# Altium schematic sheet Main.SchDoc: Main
size A4; Date: Not shown in title block; ApprovedBy: Not shown in title block; CheckedBy: Not shown in title block; Author: Not shown in title block; CompanyName: Not shown in title block; DrawnBy: Hely Zhang; Engineer: Hely Zhang; Organization: Texas Instrument; Address1: Not shown in title block; Address2: Not shown in title block; Address3: Not shown in title block; Address4: Not shown in title block; DocumentNumber: 2; Revision: Use project parameter SCH_Rev; SheetNumber: 2; SheetTotal: 6; PageSetup: Record=PageOptions¦CenterHorizontal=True¦CenterVertical=True¦PrintScale=1.00¦XCorrection=1.00¦YCorrection=1.00¦PrintKind=0¦BorderSize=5000000¦LeftOffset=0¦BottomOffset=0¦Orientation=2¦PaperLength=1000¦PaperWidth=1000¦Scale=100¦PaperSource=15¦PrintQuality=600¦MediaType=1¦DitherType=10¦PaperKind=Letter¦PrintScaleMode=1
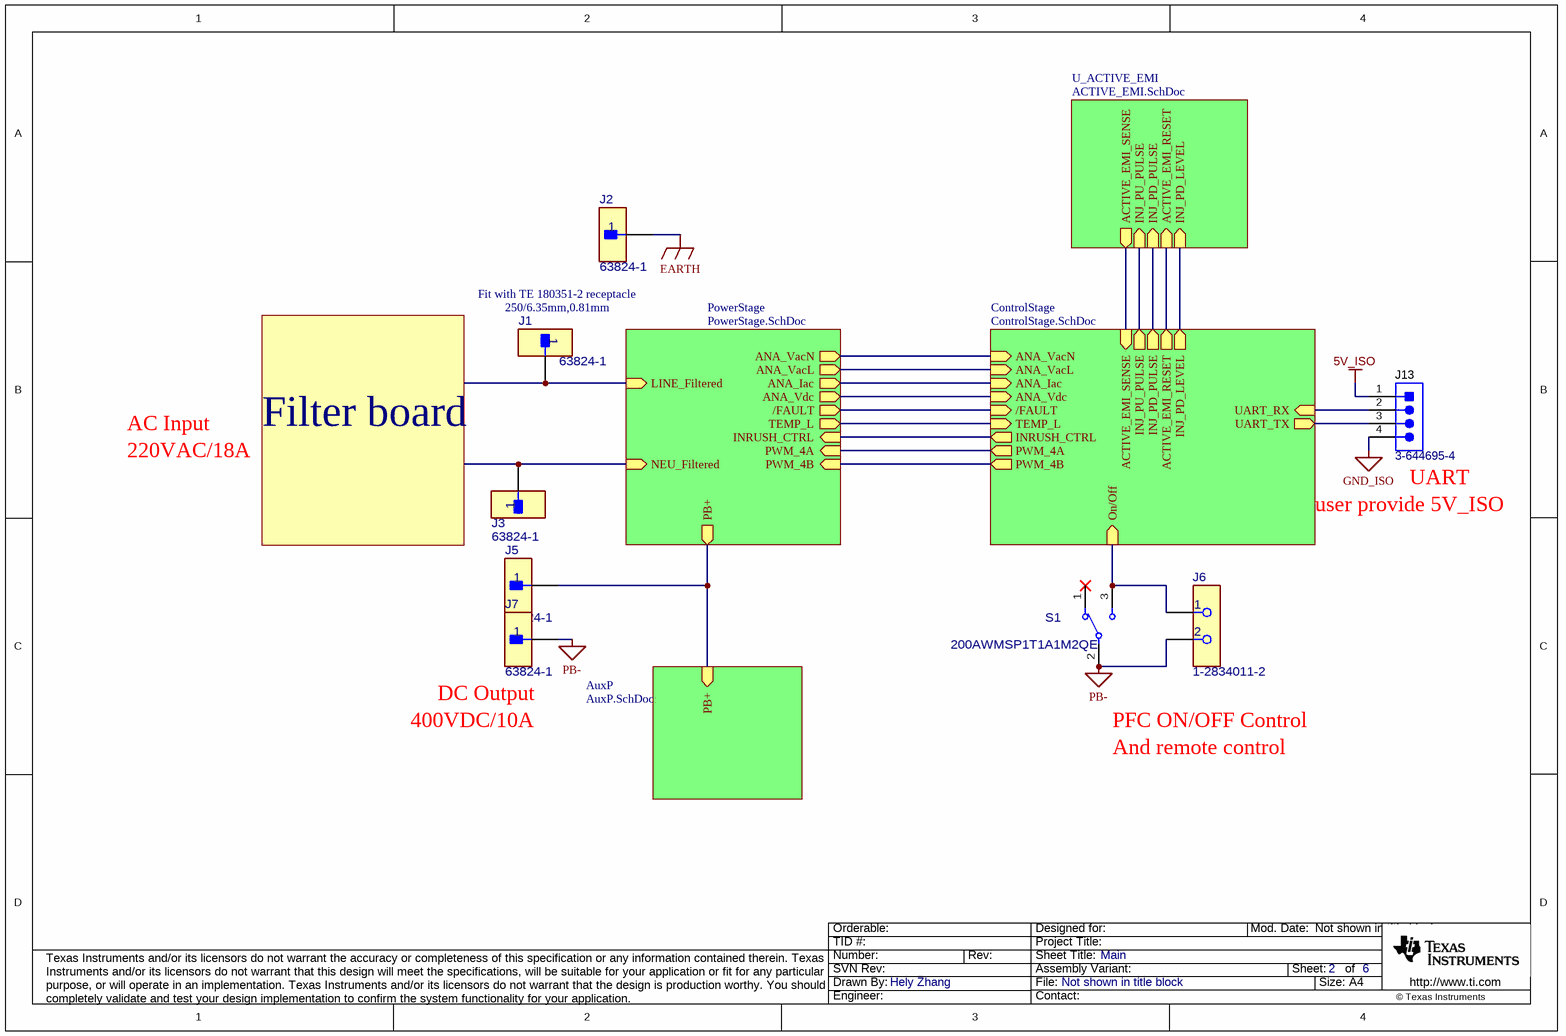
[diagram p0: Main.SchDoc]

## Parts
J1  63824-1  [FP-63824-1_CONN_7MM92_3MM11-MFG]
J2  63824-1  [FP-63824-1_CONN_7MM92_3MM11-MFG]
J3  63824-1  [FP-63824-1_CONN_7MM92_3MM11-MFG]
J5  63824-1  [FP-63824-1_CONN_7MM92_3MM11-MFG]
J6  1-2834011-2  [FP-1-2834011-2_HDR2-MFG]
J7  63824-1  [FP-63824-1_CONN_7MM92_3MM11-MFG]
J13  3-644695-4  [TE_644695-4]
S1  200AWMSP1T1A1M2QE  [FP-200AWMSP1T1A1M2QE_PTH_SW_8MM13_5MM08-MFG]

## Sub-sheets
AuxP = AuxP.SchDoc: PB+ (in)
ControlStage = ControlStage.SchDoc: ANA_Vdc (in), ANA_Iac (in), /FAULT (in), TEMP_L (in), UART_RX (in), UART_TX (out), On/Off (in), ANA_VacL (in), ANA_VacN (in), INRUSH_CTRL (out), PWM_4B (out), PWM_4A (out), ACTIVE_EMI_SENSE (in), INJ_PU_PULSE (out), INJ_PD_PULSE (out), INJ_PD_LEVEL (out), ACTIVE_EMI_RESET (out)
PowerStage = PowerStage.SchDoc: ANA_Vdc (out), ANA_Iac (out), /FAULT (out), PB+ (out), LINE_Filtered (in), NEU_Filtered (in), TEMP_L (out), ANA_VacL (out), ANA_VacN (out), INRUSH_CTRL (in), PWM_4A (in), PWM_4B (in)
U_ACTIVE_EMI = ACTIVE_EMI.SchDoc: INJ_PD_LEVEL (in), ACTIVE_EMI_RESET (in), INJ_PD_PULSE (in), INJ_PU_PULSE (in), ACTIVE_EMI_SENSE (out)

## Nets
5V_ISO: J13.1
EARTH: J2.1
GND_ISO: J13.4
PB-: J6.2 J7.1 S1.2(COM)
NetJ1_1: J1.1 ; sheet PowerStage/LINE_Filtered
NetJ3_1: J3.1 ; sheet PowerStage/NEU_Filtered
NetJ5_1: J5.1 ; sheet AuxP/PB+, sheet PowerStage/PB+
NetJ6_1: J6.1 S1.3 ; sheet ControlStage/On/Off
NetJ13_2: J13.2 ; sheet ControlStage/UART_RX
NetJ13_3: J13.3 ; sheet ControlStage/UART_TX
(unnamed): sheet ControlStage/ANA_Vdc, sheet PowerStage/ANA_Vdc
(unnamed): sheet ControlStage/ANA_Iac, sheet PowerStage/ANA_Iac  [a separate net that carries the same name]
(unnamed): sheet ControlStage//FAULT, sheet PowerStage//FAULT  [a separate net that carries the same name]
(unnamed): sheet ControlStage/TEMP_L, sheet PowerStage/TEMP_L  [a separate net that carries the same name]
(unnamed): sheet ControlStage/ANA_VacL, sheet PowerStage/ANA_VacL  [a separate net that carries the same name]
(unnamed): sheet ControlStage/ANA_VacN, sheet PowerStage/ANA_VacN  [a separate net that carries the same name]
(unnamed): sheet ControlStage/INRUSH_CTRL, sheet PowerStage/INRUSH_CTRL  [a separate net that carries the same name]
(unnamed): sheet ControlStage/PWM_4B, sheet PowerStage/PWM_4B  [a separate net that carries the same name]
(unnamed): sheet ControlStage/PWM_4A, sheet PowerStage/PWM_4A  [a separate net that carries the same name]
(unnamed): sheet ControlStage/ACTIVE_EMI_SENSE, sheet U_ACTIVE_EMI/ACTIVE_EMI_SENSE  [a separate net that carries the same name]
(unnamed): sheet ControlStage/INJ_PU_PULSE, sheet U_ACTIVE_EMI/INJ_PU_PULSE  [a separate net that carries the same name]
(unnamed): sheet ControlStage/INJ_PD_PULSE, sheet U_ACTIVE_EMI/INJ_PD_PULSE  [a separate net that carries the same name]
(unnamed): sheet ControlStage/INJ_PD_LEVEL, sheet U_ACTIVE_EMI/INJ_PD_LEVEL  [a separate net that carries the same name]
(unnamed): sheet ControlStage/ACTIVE_EMI_RESET, sheet U_ACTIVE_EMI/ACTIVE_EMI_RESET  [a separate net that carries the same name]

Not connected (* = marked no-connect by the designer): S1 1*

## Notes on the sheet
- Fit with TE 180351-2 receptacle
- (near J1) 250/6.35mm,0.81mm
- AC Input
- Filter board
- 220VAC/18A
- user provide 5V_ISO
- (near J13) UART
- (near J7) DC Output
- 400VDC/10A
- PFC ON/OFF Control
- And remote control

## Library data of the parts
J1-J3 J5 J7 = CMP-0089624-1: Manufacturer: TE Connectivity; SizeZ_mm: 10.71mm; Conn Gender: Male; Conn Orientation: Straight; AEC Qualified: No; Import Ts: 1521847382; ContactFinish: Tin,Nickel; Current_A: 20A; Ciiva Ids: 766930
J6 = CMP-0092874-1: Manufacturer: TE Connectivity AMP Connectors; Min Wire Gauge: 20; Voltage_V: 300V; SizeZ_mm: 13.1mm; Conn Gender: Female; ContactFinish: Tin,Nickel; Is Female: yes; Max Wire Gauge: 14; DUT-Pitch_mm: 3.5mm; Current_A: 6A; Conn Orientation: Vertical; AEC Qualified: No; Row_Count: 1
J13 = CMP-0054954-3: Header, 100mil, 4x1, Tin, TH; Manufacturer: TE Connectivity; CNHeader: TRUE; CT: FALSE
S1 = CMP-0091791-1: Toggle Switch SPDT Through Hole  3A 120V; Manufacturer: E-Switch; VDC_V: 28V; AEC Qualified: No; Electromechanical Life: 50000Cycles; SizeZ_mm: 24.2mm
